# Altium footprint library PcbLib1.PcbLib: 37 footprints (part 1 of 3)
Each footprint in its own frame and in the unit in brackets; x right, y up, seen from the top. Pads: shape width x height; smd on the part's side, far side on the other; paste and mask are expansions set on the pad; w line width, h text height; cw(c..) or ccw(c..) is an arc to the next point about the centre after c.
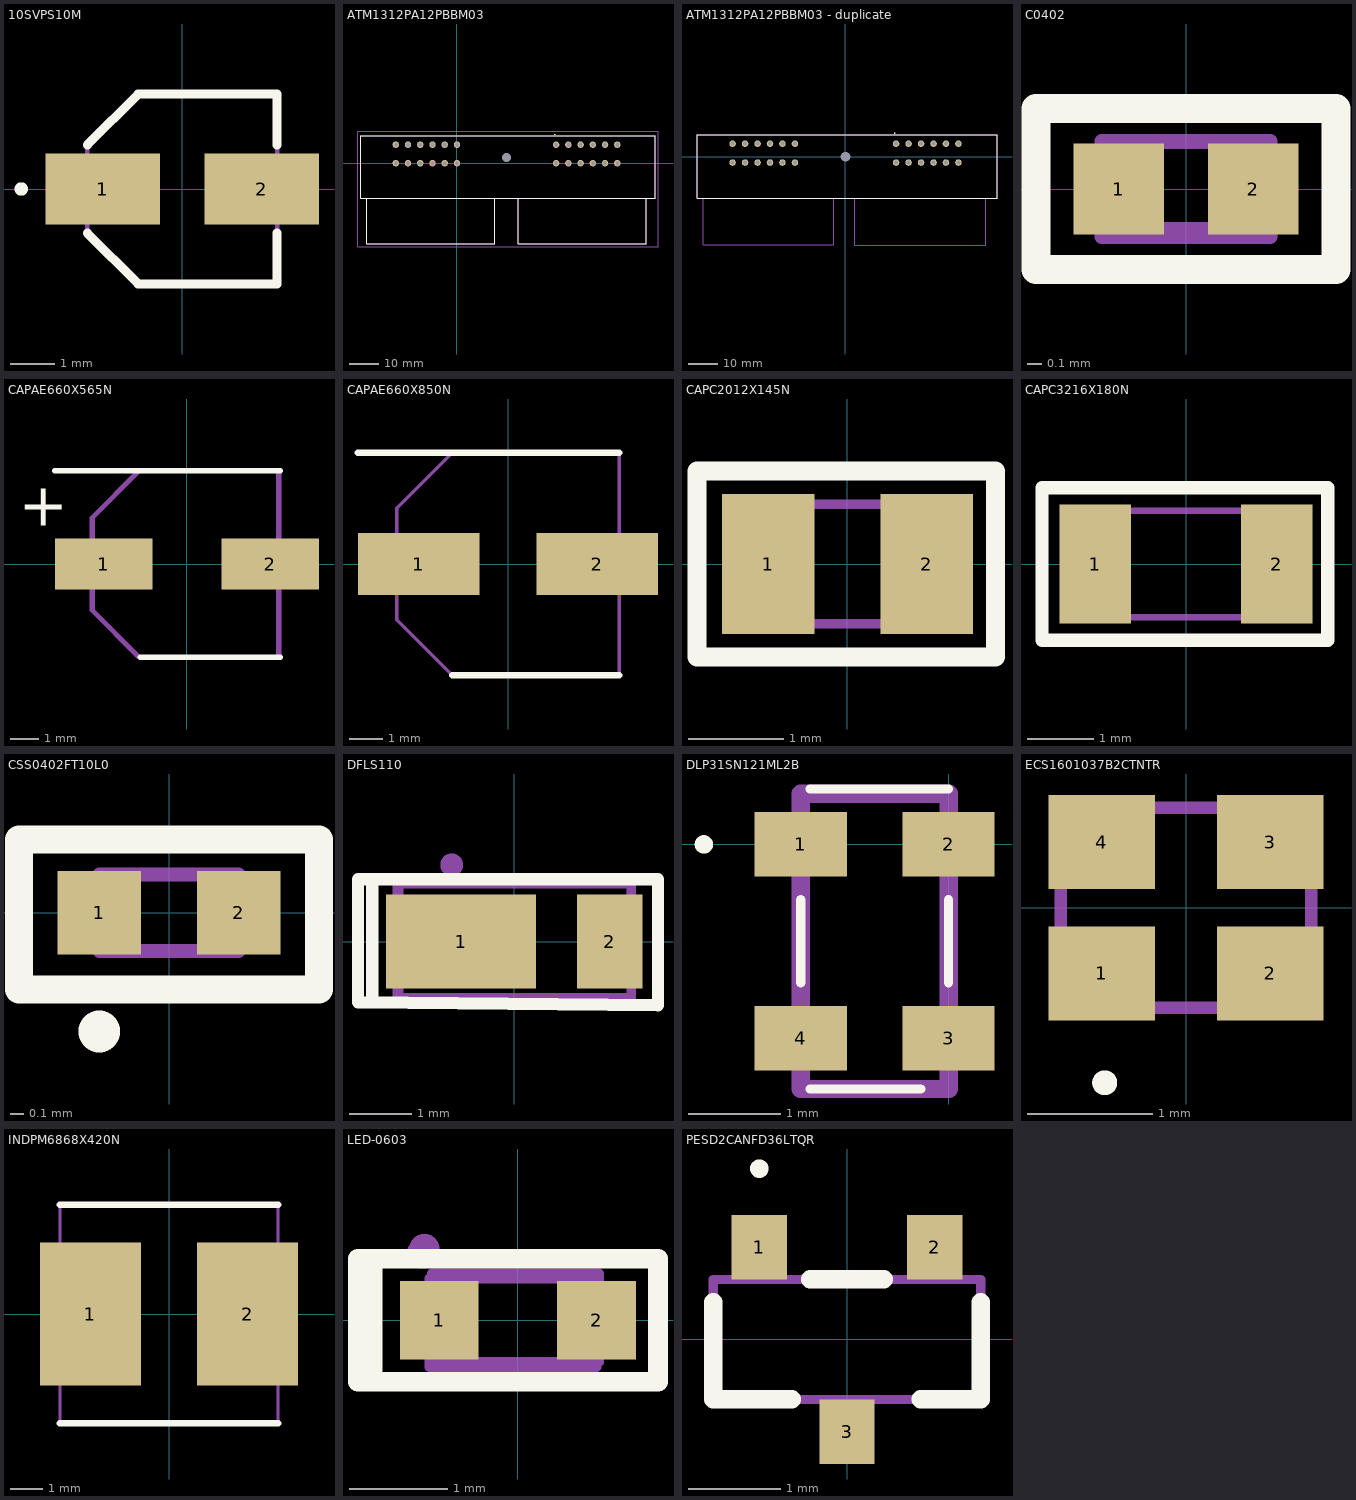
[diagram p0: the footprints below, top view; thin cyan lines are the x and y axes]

## 10SVPS10M [mm]
pads (2):
  rect 2.6x1.6 smd: 1(-1.8,0) 2(1.8,0)
Top Overlay:
  lines w0.2: -2.15,-1 -1,-2.15 2.15,-2.15 2.15,-1 ; -2.15,1 -1,2.15 2.15,2.15 2.15,1 ; -3.7,0 cw(c-3.65,0) -3.6,0 ; -3.7,0 ccw(c-3.65,0) -3.6,0 ; -3.7,0 cw(c-3.65,0) -3.6,0
Mechanical 13:
  lines w0.1: -2.15,-1 -2.15,1 -1,2.15 2.15,2.15 2.15,-2.15 -1,-2.15 -2.15,-1
  text ".Designator" at -2.182,-0.106 h1
3D body "4SVP33M.stp": height 5.43, standoff 0.03, extent -2.5,-2.15 2.5,2.15

## ATM1312PA12PBBM03 [mm]
pads (25):
  round 2.2 hole 1.4: A1(0,0) A2(-4.2,0) A3(-8.4,0) A4(-12.6,0) A5(-16.8,0) A6(-21,0) A7(-21,6.35) A8(-16.8,6.35) A9(-12.6,6.35) A10(-8.4,6.35) A11(-4.2,6.35) A12(0,6.35) B1(34.05,6.35) B2(38.25,6.35) B3(42.45,6.35) B4(46.65,6.35) B5(50.85,6.35) B6(55.05,6.35) B7(55.05,0) B8(50.85,0) B9(46.65,0) B10(42.45,0) B11(38.25,0) B12(34.05,0)
  round 1.6 hole 3.2 unplated: MH1(17.02,1.98)
Top Overlay:
  lines w0.1: -30.98,-11.95 -30.98,-27.65 13.02,-27.65 13.02,-11.95 ; 21.02,-11.95 21.02,-27.65 65.02,-27.65 65.02,-11.95 ; -32.975,-11.95 -32.975,9.35 68.025,9.35 68.025,-11.95 -32.975,-11.95 ; 33.55,9.85 cw(c33.55,9.9) 33.55,9.95 cw(c33.55,9.9) 33.55,9.85
Mechanical 15:
  lines w0.2: -30.98,-11.95 -30.98,-27.65 13.02,-27.65 13.02,-11.95 ; 21.02,-11.95 21.02,-27.65 65.02,-27.65 65.02,-11.95 ; -32.975,-11.95 -32.975,9.35 68.025,9.35 68.025,-11.95 -32.975,-11.95
Mechanical 20:
  lines w0.1: -33.975,-28.65 -33.975,10.95 69.025,10.95 69.025,-28.65 -33.975,-28.65
3D body "c-atm13-12pa-12pb-bm03-3d-c3d.STP": height 15.1, standoff -19.9, extent -36.243,-25.851 72.057,11.049

## ATM1312PA12PBBM03 - duplicate [mm]
pads (25):
  round 2.2 hole 1.4: A1(-17.02,-1.98) A2(-21.22,-1.98) A3(-25.42,-1.98) A4(-29.62,-1.98) A5(-33.82,-1.98) A6(-38.02,-1.98) A7(-38.02,4.37) A8(-33.82,4.37) A9(-29.62,4.37) A10(-25.42,4.37) A11(-21.22,4.37) A12(-17.02,4.37) B1(17.03,4.37) B2(21.23,4.37) B3(25.43,4.37) B4(29.63,4.37) B5(33.83,4.37) B6(38.03,4.37) B7(38.03,-1.98) B8(33.83,-1.98) B9(29.63,-1.98) B10(25.43,-1.98) B11(21.23,-1.98) B12(17.03,-1.98)
  round 1.6 hole 3.2 unplated: ""(0,0)
Top Overlay:
  lines w0.1: -49.995,-13.93 -49.995,7.37 51.005,7.37 51.005,-13.93 -49.995,-13.93 ; 16.53,7.87 cw(c16.53,7.92) 16.53,7.97 cw(c16.53,7.92) 16.53,7.87
Mechanical 13:
  lines w0.2: -47.943,-13.93 -47.943,-29.63 -3.943,-29.63 -3.943,-13.93 ; 3.181,-14.057 3.181,-29.757 47.181,-29.757 47.181,-14.057 ; -49.995,-13.93 -49.995,7.37 51.005,7.37 51.005,-13.93 -49.995,-13.93
  text ".Designator" at -6.098,-7.187 h1.52
3D body "ATM13-12PA-12PB-BM03.stp": height 27.1, standoff -7.9, extent -54.059,-30.653 54.241,6.247

## C0402 [mm]
pads (2):
  rect 0.62x0.62 smd: 1(-0.46,0) 2(0.46,0)
Top Overlay:
  lines w0.2: -1.025,-0.55 -1.025,0.55 1.025,0.55 1.025,-0.55 -1.025,-0.55
Mechanical 13:
  lines w0.1: -0.55,-0.275 -0.55,0.325 0.525,0.325 0.525,-0.275 -0.55,-0.275
  text ".Designator" at -1.125,-0.317 h1
Mechanical 29:
  lines w0.1: -0.575,-0.325 0.575,-0.325 0.575,0.325 -0.575,0.325 -0.575,-0.325
  text "'.Designator'" at -0.7,-0.158 h0.5
Mechanical 30:
  text ".Comment" at -1.075,-1.05 h0.5
3D body "C0402C104K4RAC-TU.stp": height 0.55, standoff 0, extent -0.525,-0.275 0.525,0.275

## CAPAE660X565N [mm]
pads (2):
  rect 3.45x1.8 smd: 1(-2.95,0) 2(2.95,0)
Top Overlay:
  lines w0.2: -4.675,3.3 3.3,3.3 ; -1.65,-3.3 3.3,-3.3
  text "+" at -5.946,1.35 h1.52
Mechanical 13:
  lines w0.1: -3.4,-1.65 -3.4,1.65 -1.75,3.3 3.2,3.3 3.2,-3.3 -1.75,-3.3 -3.4,-1.65
  text ".Designator" at -3.321,-0.763 h1.52
Mechanical 29:
  lines w0.1: -3.3,-1.65 -1.65,-3.3 3.3,-3.3 3.3,3.3 -1.65,3.3 -3.3,1.65 -3.3,-1.65
  text ".Designator" at -3.221,-0.763 h1.52
Mechanical 30:
  text ".Comment" at -3.4,-2.125 h1
3D body "EXV106M050A9GAA.stp": height 5.66, standoff 0, extent -3.8,-3.4 3.8,3.4

## CAPAE660X850N [mm]
pads (2):
  rect 3.6x1.85 smd: 1(-2.65,0) 2(2.65,0)
Top Overlay:
  lines w0.2: -4.45,3.3 3.3,3.3 ; -1.65,-3.3 3.3,-3.3
Mechanical 13:
  lines w0.1: -3.3,-1.65 -3.3,1.65 -1.65,3.3 3.3,3.3 3.3,-3.3 -1.65,-3.3 -3.3,-1.65
  text ".Designator" at -3.457,-0.406 h1
3D body "AHA0608150M050R.stp": height 8, standoff 0.03, extent -3.65,-3.3 3.65,3.3

## CAPC2012X145N [mm]
pads (2):
  rect 0.97x1.47 smd: 1(-0.83,0) 2(0.83,0)
Top Overlay:
  lines w0.2: -1.575,-0.975 -1.575,0.975 1.55,0.975 1.55,-0.975 -1.575,-0.975
Mechanical 13:
  lines w0.1: -1,-0.625 -1,0.625 1,0.625 1,-0.625 -1,-0.625
  text ".Designator" at -1.407,-0.456 h1
3D body "GRM21BR71C475KE51L.stp": height 1.45, standoff 0, extent -1,-0.625 1,0.625

## CAPC3216X180N [mm]
pads (2):
  rect 1.07x1.78 smd: 1(-1.36,0) 2(1.36,0)
Top Overlay:
  lines w0.2: 2.125,1.125 2.125,-1.143 -2.159,-1.143 -2.159,1.143 2.125,1.143
Mechanical 13:
  lines w0.1: -1.6,-0.8 -1.6,0.8 1.6,0.8 1.6,-0.8 -1.6,-0.8
  text ".Designator" at -1.832,-0.356 h1
3D body "EMK316BJ475ML-T.stp": height 1.8, standoff 0, extent -1.6,-0.8 1.6,0.8

## CSS0402FT10L0 [mm]
pads (2):
  rect 0.6x0.6 smd: 1(-0.5,0) 2(0.5,0)
Top Overlay:
  lines w0.2: -0.5,-0.9 cw(c-0.5,-0.85) -0.5,-0.8 ; -0.5,-0.9 ccw(c-0.5,-0.85) -0.5,-0.8 ; -0.5,-0.9 cw(c-0.5,-0.85) -0.5,-0.8 ; -1.075,-0.55 -1.075,0.525 1.075,0.525 1.075,-0.55 -1.075,-0.55
Mechanical 13:
  lines w0.1: -0.5,-0.275 -0.5,0.275 0.5,0.275 0.5,-0.275 -0.5,-0.275
  text ".Designator" at -1.757,-0.306 h1
3D body "RES_CSS0402__005-_02OHM_STP.step": height 0.41, standoff 0, extent -0.572,-0.356 0.572,0.356

## DFLS110 [mm]
pads (2):
  rect 2.4x1.5 smd: 1(-0.85,0)
  rect 1.05x1.5 smd: 2(1.525,0)
Top Overlay:
  lines w0.2: -2.275,-0.95 -2.275,1 -2.5,1 ; -2.5,1 2.3,1 2.3,-1.023 -2.5,-0.969 -2.5,1
Mechanical 13:
  lines w0.1: -1.825,-0.875 -1.825,0.9 1.85,0.9 1.85,-0.875 -1.825,-0.875
  text ".Designator" at -1.625,-0.342 h1
Mechanical 29:
  circle w0.254: c-1,1.225 r0.056
  lines w0.1: -1.9,-0.925 -1.9,0.925 1.9,0.925 1.9,-0.925 -1.9,-0.925
  text ".Designator" at -1.7,-0.283 h0.5
Mechanical 30:
  text ".Comment" at -1.775,-1.3 h0.5
3D body "DFLS1100-7.stp": height 0.98, standoff 0, extent -1.85,-0.9 1.85,0.88

## DLP31SN121ML2B [mm]
pads (4):
  rect 1x0.7 smd: 1(-1.6,0) 2(0,0) 3(0,-2.1) 4(-1.6,-2.1)
Top Overlay:
  lines w0.1: -1.6,-1.5 -1.6,-0.6 ; -1.5,-2.65 -0.3,-2.65 ; -1.5,0.6 0,0.6 ; 0,-1.5 0,-0.6 ; -2.7,0 ccw(c-2.65,0) -2.6,0 ccw(c-2.65,0) -2.7,0
Mechanical 13:
  lines w0.2: -1.6,-2.65 0,-2.65 0,0.55 -1.6,0.55 -1.6,-2.65
  text ".Designator" at -2.3,-1.417 h1
3D body "DLP31SN121ML2L.stp": height 1.4, standoff 0, extent -2.03,-2.65 0.43,0.55

## ECS1601037B2CTNTR [mm]
pads (4):
  rect 0.85x0.75 smd: 1(-0.675,-0.525) 2(0.675,-0.525) 3(0.675,0.525) 4(-0.675,0.525)
Top Overlay:
  lines w0.1: -0.7,-1.4 cw(c-0.65,-1.4) -0.6,-1.4 cw(c-0.65,-1.4) -0.7,-1.4
Mechanical 13:
  lines w0.1: -1,-0.8 1,-0.8 1,0.8 -1,0.8 -1,-0.8
  text ".Designator" at -1.207,-0.406 h1
3D body "ECS-160-10-37B2-CTN-TR.stp": height 0.6, standoff 0, extent -1.025,-0.825 1.025,0.825

## INDPM6868X420N [mm]
pads (2):
  rect 3.15x4.45 smd: 1(-2.45,0) 2(2.45,0)
Top Overlay:
  lines w0.2: -3.4,-3.4 3.4,-3.4 ; -3.4,3.4 3.4,3.4
Mechanical 13:
  lines w0.1: -3.4,-3.4 3.4,-3.4 3.4,3.4 -3.4,3.4 -3.4,-3.4
  text ".Designator" at -3.532,-0.206 h1
3D body "SRR6838A-150M.stp": height 4.2, standoff 0, extent -3.4,-3.4 3.4,3.4

## LED-0603 [mm]
pads (2):
  rect 0.8x0.8 smd: 1(-0.8,0) 2(0.8,0)
Top Overlay:
  lines w0.2: -1.475,-0.5 -1.475,0.512 ; -1.625,-0.625 -1.625,0.625 1.425,0.625 1.425,-0.625 -1.625,-0.625
Mechanical 13:
  circle w0.254: c-0.95,0.725 r0.025
  lines w0.1: -0.875,-0.425 0.825,-0.425 0.825,0.475 -0.875,0.475 -0.875,-0.425
  text ".Designator" at -0.55,-0.208 h0.5
Mechanical 29:
  circle w0.254: c-0.975,0.675 r0.025
  lines w0.1: -0.9,-0.475 0.8,-0.475 0.8,0.425 -0.9,0.425 -0.9,-0.475
  text ".Designator" at -0.575,-0.258 h0.5
Mechanical 30:
  text ".Comment" at -1.35,-0.95 h0.5
3D body "150060AS75000.STEP": height 0.81, standoff 0.01, extent -0.85,-0.425 0.75,0.375

## PCBComponent_1 [mm]

## PESD2CANFD36LTQR [mm]
pads (3):
  rect 0.6x0.7 smd: 1(-0.95,1) 2(0.95,1) 3(0,-1)
Top Overlay:
  lines w0.1: -0.95,1.8 cw(c-0.95,1.85) -0.95,1.9 cw(c-0.95,1.85) -0.95,1.8
  lines w0.2: -1.45,0.4 -1.45,-0.65 -0.6,-0.65 ; -0.4,0.65 0.4,0.65 ; 0.8,-0.65 1.45,-0.65 1.45,0.4
Mechanical 13:
  lines w0.1: -1.45,-0.65 -1.45,0.65 1.45,0.65 1.45,-0.65 -1.45,-0.65
  text ".Designator" at -1.3,-0.283 h0.5
3D body "PESD2CANFD36LT-QR.stp": height 1.2, standoff 0, extent -1.45,-1.29 1.45,1.29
